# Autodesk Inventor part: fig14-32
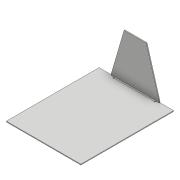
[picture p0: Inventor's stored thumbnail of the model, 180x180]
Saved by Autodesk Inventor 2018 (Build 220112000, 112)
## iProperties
Created: 2017-05
Part Number: fig14-32
Material: Generic
Document SubType Name: Sheet Metal
Designer: CADCIM 00
Density: 1 g/cm^3
Sheet Metal Rule: Default_mm
Appearance: Default
Author: CADCIM 00
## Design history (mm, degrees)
node "Face1"
  sketch "Sketch1"
    geometry: L1 (0, 0)-(45.552, 0); L2 (45.552, 0)-(45.552, 56.721); L3 (45.552, 56.721)-(0, 56.721); L4 (0, 56.721)-(0, 0)
    constraints: 8 end point, 2 parallel, 1 horizontal, 1 perpendicular
node "Face2"
  sketch "Sketch2"
    geometry: L1 (10.232, -9.455)-(15.772, -28.394); L2 (15.772, -28.394)-(29.3, -28.394); L3 (29.3, -28.394)-(34.84, -9.455); L4 (34.84, -9.455)-(10.232, -9.455); 1 further point
    constraints: 8 end point, 1 horizontal, 1 parallel
body "Solid1"
face "Plate1" dims "d0" = 0.5 (= Thickness)
face "Plate2" dims "d0" = 0.5 (= Thickness), "d1" = 0.5 (= BendRadius), "d2" = 0.5 (= BendReliefWidth), "d4" = 1 (= MinimumRemnant)
bend "Bend1" dims "d0" = 0.5 (= Thickness), "d1" = 0.5 (= BendRadius), "d2" = 0.5 (= BendReliefWidth), "d3" = 0.25 (= BendReliefDepth), "d4" = 1 (= MinimumRemnant), "d5" = 0.5 (= TransitionRadius), "SeamGap" = 0.01
other parameters: "Thickness" = 0.5, "BendRadius" = 0.5 (= Thickness), "BendReliefWidth" = 0.5 (= Thickness), "BendReliefDepth" = 0.25 (= 0.5 x Thickness), "CornerReliefSize" = 2 (= 4 x Thickness), "MinimumRemnant" = 1 (= 2 x Thickness), "TransitionRadius" = 0.5 (= BendRadius), "JacobiRadiusSize" = 0.5 (= BendRadius), "GapSize" = 0.5 (= Thickness)
